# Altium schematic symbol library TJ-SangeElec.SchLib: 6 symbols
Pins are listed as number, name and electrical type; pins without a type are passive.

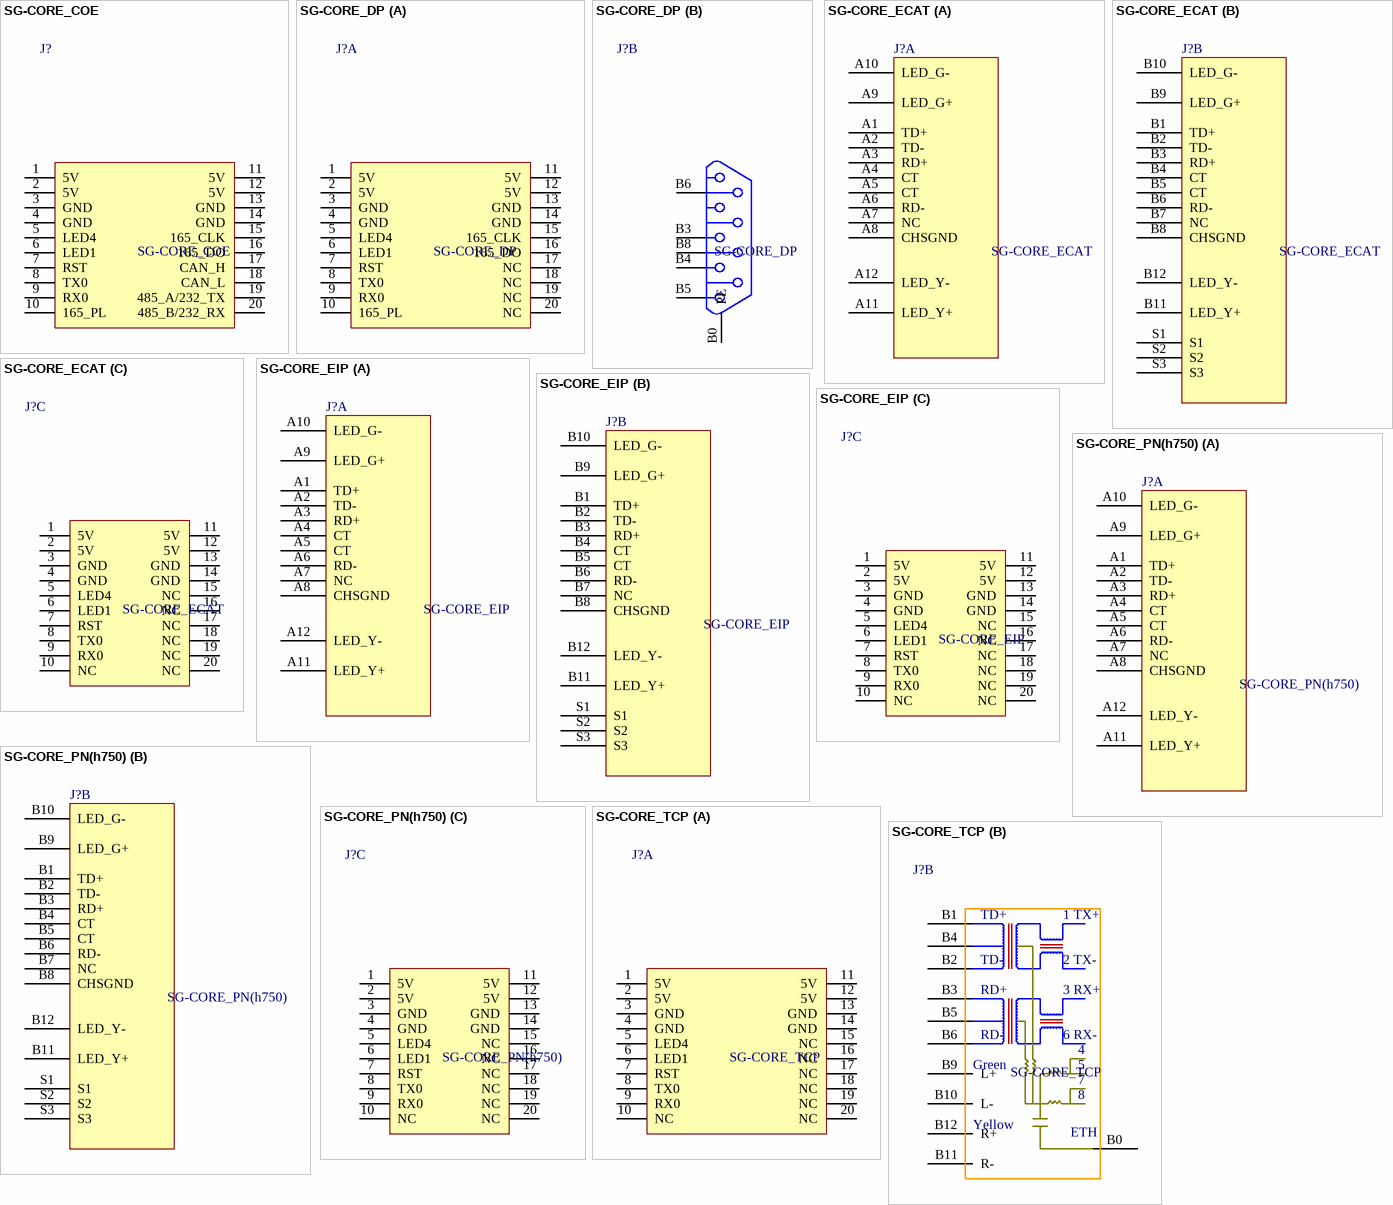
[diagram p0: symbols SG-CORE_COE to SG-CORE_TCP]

## SG-CORE_COE
designator J?
CANOPEN核心板
footprint SG-CORE_COE (CANOPEN核心板)
pins: 1 5V, 2 5V, 3 GND, 4 GND, 5 LED4, 6 LED1, 7 RST, 8 TX0, 9 RX0, 10 165_PL, 11 5V, 12 5V, 13 GND, 14 GND, 15 165_CLK, 16 165_DO, 17 CAN_H, 18 CAN_L, 19 485_A/232_TX, 20 485_B/232_RX

## SG-CORE_DP
designator J?
Profibus DP核心板
footprint SG-CORE_DP (Profibus DP核心板)
part A pins: 1 5V, 2 5V, 3 GND, 4 GND, 5 LED4, 6 LED1, 7 RST, 8 TX0, 9 RX0, 10 165_PL, 11 5V, 12 5V, 13 GND, 14 GND, 15 165_CLK, 16 165_DO, 17 NC, 18 NC, 19 NC, 20 NC
part B pins: B0 PE, B3 PRO_A, B4 PRO_RTS, B5 GND, B6 3V3, B8 PRO_B

## SG-CORE_ECAT
designator J?
EtherCAT核心板
footprint SG-CORE_ECAT (EtherCAT核心板)
part A pins: A1 TD+, A2 TD-, A3 RD+, A4 CT, A5 CT, A6 RD-, A7 NC, A8 CHSGND, A9 LED_G+, A10 LED_G-, A11 LED_Y+, A12 LED_Y-
part B pins: B1 TD+, B2 TD-, B3 RD+, B4 CT, B5 CT, B6 RD-, B7 NC, B8 CHSGND, B9 LED_G+, B10 LED_G-, B11 LED_Y+, B12 LED_Y-, S1, S2, S3
part C pins: 1 5V, 2 5V, 3 GND, 4 GND, 5 LED4, 6 LED1, 7 RST, 8 TX0, 9 RX0, 10 NC, 11 5V, 12 5V, 13 GND, 14 GND, 15 NC, 16 NC, 17 NC, 18 NC, 19 NC, 20 NC

## SG-CORE_EIP
designator J?
EtherNet核心板
footprint SG-CORE_EIP (EtherNet核心板)
part A pins: A1 TD+, A2 TD-, A3 RD+, A4 CT, A5 CT, A6 RD-, A7 NC, A8 CHSGND, A9 LED_G+, A10 LED_G-, A11 LED_Y+, A12 LED_Y-
part B pins: B1 TD+, B2 TD-, B3 RD+, B4 CT, B5 CT, B6 RD-, B7 NC, B8 CHSGND, B9 LED_G+, B10 LED_G-, B11 LED_Y+, B12 LED_Y-, S1, S2, S3
part C pins: 1 5V, 2 5V, 3 GND, 4 GND, 5 LED4, 6 LED1, 7 RST, 8 TX0, 9 RX0, 10 NC, 11 5V, 12 5V, 13 GND, 14 GND, 15 NC, 16 NC, 17 NC, 18 NC, 19 NC, 20 NC

## SG-CORE_PN(h750)
designator J?
Profinet(h750)核心板
footprint SG-CORE_PN(h750) (Profinet(h750)核心板)
part A pins: A1 TD+, A2 TD-, A3 RD+, A4 CT, A5 CT, A6 RD-, A7 NC, A8 CHSGND, A9 LED_G+, A10 LED_G-, A11 LED_Y+, A12 LED_Y-
part B pins: B1 TD+, B2 TD-, B3 RD+, B4 CT, B5 CT, B6 RD-, B7 NC, B8 CHSGND, B9 LED_G+, B10 LED_G-, B11 LED_Y+, B12 LED_Y-, S1, S2, S3
part C pins: 1 5V, 2 5V, 3 GND, 4 GND, 5 LED4, 6 LED1, 7 RST, 8 TX0, 9 RX0, 10 NC, 11 5V, 12 5V, 13 GND, 14 GND, 15 NC, 16 NC, 17 NC, 18 NC, 19 NC, 20 NC

## SG-CORE_TCP
designator J?
TCP核心板
footprint SG-CORE_TCP (TCP核心板)
part A pins: 1 5V, 2 5V, 3 GND, 4 GND, 5 LED4, 6 LED1, 7 RST, 8 TX0, 9 RX0, 10 NC, 11 5V, 12 5V, 13 GND, 14 GND, 15 NC, 16 NC, 17 NC, 18 NC, 19 NC, 20 NC
part B pins: B0, B1, B2, B3, B4, B5, B6, B9 L+, B10 L-, B11 R-, B12 R+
